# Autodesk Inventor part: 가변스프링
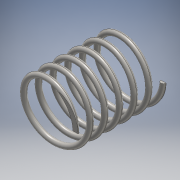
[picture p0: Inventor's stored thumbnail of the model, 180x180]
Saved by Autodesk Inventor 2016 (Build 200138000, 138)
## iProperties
Created: 2018-11
Part Number: 가변스프링
Material: 스테인레스 스틸
Document SubType Name: Modeling
Designer: user
Density: 8 g/cm^3
Appearance: 반연마
Mass: 84.3693 g
Surface Area: 106.586 cm^2
Volume: 10.5462 cm^3
Author: user
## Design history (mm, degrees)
sketch "스케치1"
  geometry: L1 (0, 0)-(22.5, 0); L2 (22.5, 0)-(22.5, 67.25); L3 (22.5, 67.25)-(0, 67.25); L4 (0, 67.25)-(0, 0); C1 r 2 at (22.5, 0)
  constraints: 8 end point, 2 parallel, 1 centre point, 1 coincident, 1 horizontal, 1 perpendicular
  dimensions: "d0" = 45 diameter of L2 L4; "d1" = 67.25 distance of L1.end L2.end (derived); "d2" = 4 diameter of C1
feature "코일1" sketch "스케치1" pitch "d3" = 10; turns "d5" = 6; dims "d4" = 67.25 (= d1), "d6" = 0, angle "d7" = 90 deg, angle "d8" = 90 deg, "d9" = 0, "d10" = 0
sketch "스케치2"
  geometry: L1 (67.25, -30)-(0, -30); L2 (0, -30)-(0, 30); L3 (0, 30)-(67.25, 30); L4 (67.25, 30)-(67.25, -30); 2 further points
  constraints: 8 end point, 2 parallel, 1 coincident, 1 horizontal, 1 midpoint, 1 perpendicular
  dimensions: "d11" = 60 distance of L1.end L2.end; "d12" = 67.25 distance of L1.start L1.end (= d1)
extrude "돌출1" sketch "스케치2" stored distance "d13" = 10; taper "d14" = 0 deg
node "솔리드1"
